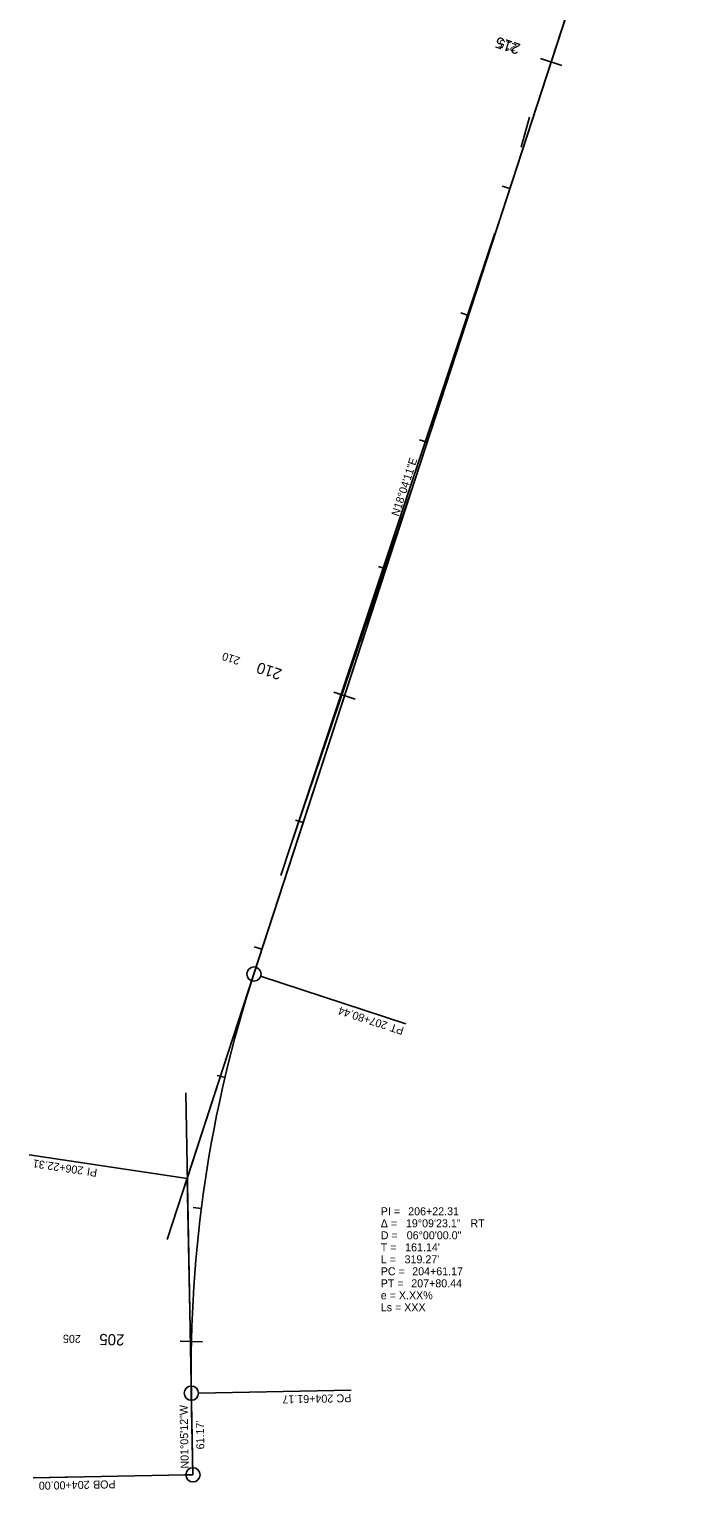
# Model space of a CAD drawing. Extents: x 1803080 to 1803655, y 572742 to 575010.
# Drawn here: x 1803080 to 1803577, y 572742 to 573837 of the extents above; entities that cross this region are included whole.
import ezdxf

# ---------------------------------------------------------------- set-up
doc = ezdxf.new("R2010")
doc.units = 0
for name, color, linetype in [('DSN_DRFT_Common-Annotations', 7, 'Continuous'), ('DSN_DRFT_DNC', 7, 'Continuous'), ('DSN_RDWY_Alignment', 7, 'Continuous'), ('DSN_RDWY_Alignment Annotation', 7, 'Continuous')]:
    doc.layers.add(name, color=color, linetype=linetype)

msp = doc.modelspace()

# ---------------------------------------------------------------- linework, layer by layer
at = {"layer": 'DSN_DRFT_DNC'}
for p, q in [((1803184, 572929.3), (1803577, 574133.6)), ((1803455.8, 573770.9), (1803449.7, 573748.5)), ((1803276.2, 573223.5), (1803429.9, 573684)), ((1803367.2, 573491.5), (1803276.2, 573223.5)), ((1803276.2, 573223.5), (1803269.1, 573202.2)), ((1803203.2, 572752.8), (1803197.8, 573039.2))]:
    msp.add_line(p, q, dxfattribs=at)
at = {"layer": 'DSN_RDWY_Alignment'}
for p, q in [((1803249, 573128.3), (1803487.2, 573858.4)), ((1803203.2, 572752.8), (1803202, 572814))]:
    msp.add_line(p, q, dxfattribs=at)
msp.add_arc((1804156.8, 572832.1), 954.9, 161.9303, 181.0867, dxfattribs=at)
msp.add_arc((1804156.8, 572832.1), 954.9, 161.9303, 181.0867, dxfattribs=at)
at = {"layer": 'DSN_RDWY_Alignment Annotation'}
for p, q in [((1803464.2, 573815), (1803480.1, 573809.7)), ((1803464.2, 573815), (1803480.1, 573809.7)), ((1803435.4, 573719.1), (1803441.1, 573717.3)), ((1803435.4, 573719.1), (1803441.1, 573717.3)), ((1803404.4, 573624.1), (1803410.1, 573622.2)), ((1803404.4, 573624.1), (1803410.1, 573622.2)), ((1803373.4, 573529), (1803379.1, 573527.1)), ((1803373.4, 573529), (1803379.1, 573527.1)), ((1803342.4, 573433.9), (1803348.1, 573432.1)), ((1803342.4, 573433.9), (1803348.1, 573432.1)), ((1803309.1, 573339.6), (1803325, 573334.4)), ((1803309.1, 573339.6), (1803325, 573334.4)), ((1803280.3, 573243.8), (1803286, 573241.9)), ((1803280.3, 573243.8), (1803286, 573241.9)), ((1803249.3, 573148.7), (1803255, 573146.9)), ((1803249.3, 573148.7), (1803255, 573146.9)), ((1803249, 573128.3), (1803249, 573128.3)), ((1803254, 573126.6), (1803363, 573091.1)), ((1803363, 573091.1), (1803363, 573091.1)), ((1803199, 572975.1), (1803230, 573070.2)), ((1803221.4, 573052.2), (1803227.3, 573050.8)), ((1803221.4, 573052.2), (1803227.3, 573050.8)), ((1803199, 572975.1), (1803080.3, 572992.8)), ((1803080.3, 572992.8), (1803080.3, 572992.8)), ((1803199, 572975.1), (1803200.9, 572875.1)), ((1803203.5, 572953.2), (1803209.5, 572952.5)), ((1803203.5, 572953.2), (1803209.5, 572952.5)), ((1803193.7, 572853), (1803210.5, 572852.6)), ((1803193.7, 572853), (1803210.5, 572852.6)), ((1803207.4, 572814.1), (1803322, 572816.3)), ((1803322, 572816.3), (1803322, 572816.3)), ((1803202, 572814), (1803202, 572814)), ((1803197.9, 572752.7), (1803083.2, 572750.5)), ((1803083.2, 572750.5), (1803119.2, 572751.2)), ((1803197.2, 572752.7), (1803203.2, 572752.8)), ((1803197.2, 572752.7), (1803203.2, 572752.8)), ((1803203.2, 572752.8), (1803203.2, 572752.8))]:
    msp.add_line(p, q, dxfattribs=at)
for centre in [(1803249, 573128.3), (1803202, 572814), (1803203.2, 572752.8)]:
    msp.add_circle(centre, 5.34, dxfattribs=at)

# ---------------------------------------------------------------- texts
at = {"layer": 'DSN_DRFT_Common-Annotations'}
msp.add_text("61.17'", height=6, rotation=91.0867, dxfattribs=at).set_placement((1803211.8, 572771.9))
at = {"layer": 'DSN_RDWY_Alignment Annotation'}
for s, height, rotation, p in [('215', 8.4, 161.9303, (1803449.7, 573825.6)), ('215', 6, 161.9303, (1803446.7, 573825.3)), ('N18°04\'11"E', 6, 71.9303, (1803357.7, 573471.1)), ('210', 6, 161.9303, (1803239.1, 573365.6)), ('210', 8.4, 161.9303, (1803270.6, 573356.6)), ('207+80.44', 6, 161.9303, (1803349.8, 573092.2)), ('PT', 6, 161.9303, (1803362.1, 573088.2)), ('206+22.31', 6, 171.5085, (1803121.3, 572983.7)), ('PI ', 6, 171.5085, (1803131.7, 572982.1)), ('205', 6, 178.757, (1803119.1, 572857.6)), ('205', 8.4, 178.757, (1803151.8, 572858.1)), ('N01°05\'12"W', 6, 91.0867, (1803200.1, 572757.5)), ('204+61.17', 6, 181.0867, (1803308.5, 572813)), ('PC', 6, 181.0867, (1803322.1, 572813.3)), ('204+00.00', 6, 181.0867, (1803125.6, 572748.3)), ('POB ', 6, 181.0867, (1803145.1, 572748.7))]:
    msp.add_text(s, height=height, rotation=rotation, dxfattribs=at).set_placement(p)
for s, p in [('PI = ', (1803344.2, 572947.4)), ('206+22.31', (1803364.8, 572947.4)), ('Δ = ', (1803344.2, 572938.4)), ('19°09\'23.1"', (1803363.1, 572938.4)), (' RT', (1803409.3, 572938.4)), ('T = ', (1803344.2, 572920.4)), ('D = ', (1803344.2, 572929.4)), ("161.14'", (1803362.5, 572920.4)), ('06°00\'00.0"', (1803363.7, 572929.4)), ('L = ', (1803344.2, 572911.4)), ("319.27'", (1803362.1, 572911.4)), ('PC = ', (1803344.2, 572902.4)), ('204+61.17', (1803367.8, 572902.4)), ('PT = ', (1803344.2, 572893.4)), ('207+80.44', (1803367.1, 572893.4)), ('e = X.XX%', (1803344.2, 572884.4)), ('Ls = XXX', (1803344.2, 572875.4))]:
    msp.add_text(s, height=6, dxfattribs=at).set_placement(p)

doc.saveas('drawing.dxf')
